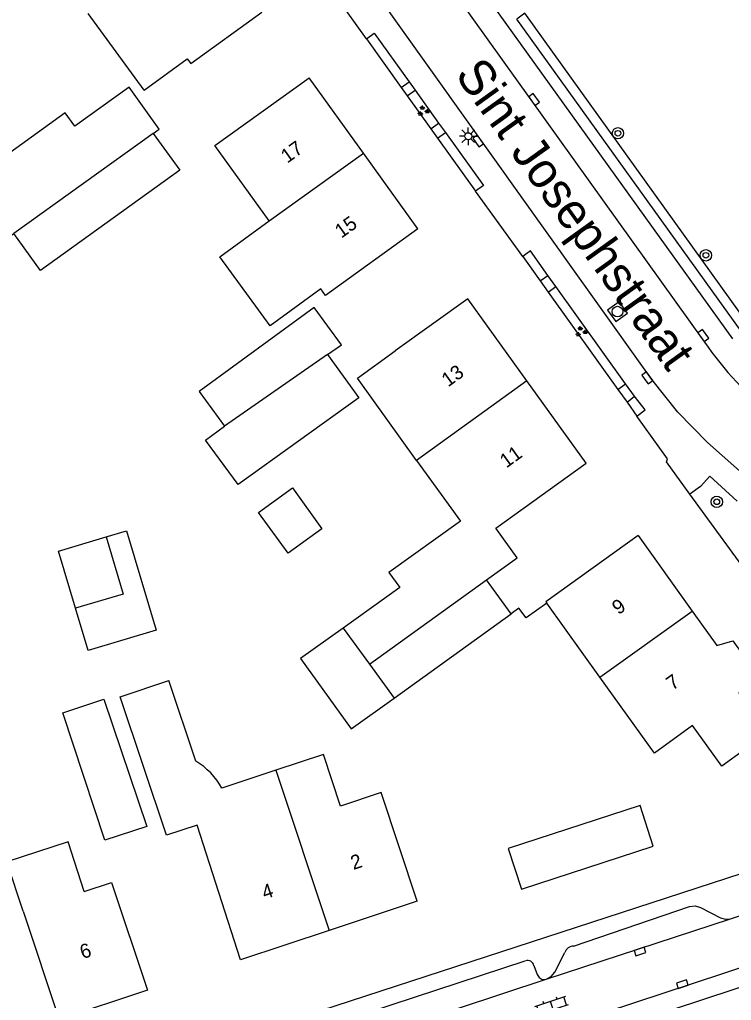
# Model space of a CAD drawing. Extents: x 136000 to 138005, y 398500 to 400500.
# Drawn here: x 137531.8 to 137581.9, y 399032.5 to 399101.6 of the extents above; entities that cross this region are included whole.
import ezdxf

# ---------------------------------------------------------------- set-up
doc = ezdxf.new("R2010")
doc.units = 0
for name, color, linetype in [('gg-afsc-muur', 7, 'Continuous'), ('gg-anno-huisnummerreeks BGT', 7, 'Continuous'), ('gg-anno-openbare ruimte label', 7, 'Continuous'), ('gg-bbg-bijgebouw', 7, 'Continuous'), ('gg-bbg-gedigitaliseerde bebouwing', 7, 'Continuous'), ('gg-bbg-gedigitaliseerde bijgebouw', 7, 'Continuous'), ('gg-bbg-hoofdgebouw', 7, 'Continuous'), ('gg-bbg-luifel en loopbrug', 7, 'Continuous'), ('gg-bbg-tussenscheiding', 7, 'Continuous'), ('gg-knt-verharding', 7, 'Continuous'), ('gg-knt-verharding nz', 7, 'Continuous'), ('gt-grn-groengrens', 7, 'Continuous'), ('gt-symb-boom', 7, 'Continuous'), ('gt-symb-groenvak', 7, 'Continuous'), ('gt-symb-klinker verharding', 7, 'Continuous'), ('gt-symb-kolk', 7, 'Continuous'), ('gt-symb-lichtmast', 7, 'Continuous'), ('gt-symb-rioolschacht', 7, 'Continuous')]:
    doc.layers.add(name, color=color, linetype=linetype)

# ---------------------------------------------------------------- blocks, each defined once
blk = doc.blocks.new('gt0-GRVAK')
at = {"layer": 'gt-symb-groenvak'}
for p, q in [((-0.11, 0.189), (-0.228, 0.24)), ((-0.182, 0.153), (0.088, 0.153)), ((-0.091, 0.211), (-0.156, 0.322)), ((-0.047, 0.214), (-0.047, 0.393)), ((-0.004, 0.211), (0.061, 0.322)), ((0.015, 0.189), (0.133, 0.24)), ((0.262, -0.052), (0.197, 0.059)), ((0.305, -0.049), (0.305, 0.13)), ((0.349, -0.052), (0.414, 0.059)), ((-0.245, -0.228), (-0.363, -0.177)), ((-0.318, -0.264), (-0.047, -0.264)), ((-0.226, -0.206), (-0.291, -0.095)), ((-0.183, -0.203), (-0.183, -0.024)), ((-0.139, -0.206), (-0.074, -0.095)), ((-0.12, -0.228), (-0.002, -0.177)), ((0.243, -0.074), (0.125, -0.023)), ((0.17, -0.11), (0.441, -0.11)), ((0.368, -0.074), (0.486, -0.023))]:
    blk.add_line(p, q, dxfattribs=at)
blk = doc.blocks.new('gt0-LMAST')
at = {"layer": 'gt-symb-lichtmast'}
for p, q in [((-0.182, 0.173), (-0.447, 0.438)), ((-0.005, 0.246), (-0.005, 0.621)), ((0.172, 0.173), (0.437, 0.438)), ((-0.255, -0.004), (-0.63, -0.004)), ((-0.182, -0.181), (-0.447, -0.446)), ((-0.005, -0.254), (-0.005, -0.629)), ((0.437, -0.446), (0.172, -0.181)), ((0.245, -0.004), (0.62, -0.004))]:
    blk.add_line(p, q, dxfattribs=at)
blk.add_circle((-0.005, -0.004), 0.25, dxfattribs=at)
blk = doc.blocks.new('gt0-KOLK')
at = {"layer": 'gt-symb-kolk'}
blk.add_lwpolyline([(0, 0), (0.375, 0), (0.375, 0.4), (-0.375, 0.4), (-0.375, 0), (0, 0)], dxfattribs=at)
blk = doc.blocks.new('gt0-RS')
at = {"layer": 'gt-symb-rioolschacht'}
blk.add_lwpolyline([(-0.5, -0.5), (0.5, -0.5), (0.5, 0.5), (-0.5, 0.5)], close=True, dxfattribs=at)
blk.add_circle((0, 0), 0.375, dxfattribs=at)
blk = doc.blocks.new('gt0-BOOM')
at = {"layer": 'gt-symb-boom'}
for radius in [0.4, 0.2]:
    blk.add_circle((0, 0), radius, dxfattribs=at)
blk = doc.blocks.new('gt0-KL1')
at = {"layer": 'gt-symb-klinker verharding'}
for p, q in [((-1.15, 0.3), (1.15, 0.3)), ((-1, -0.3), (-1, 0.3)), ((-0.5, 0.3), (-0.5, 0.45)), ((0, -0.3), (0, 0.3)), ((0.5, 0.3), (0.5, 0.45)), ((1, -0.3), (1, 0.3)), ((-1.15, -0.3), (1.15, -0.3)), ((-0.5, -0.45), (-0.5, -0.3)), ((0.5, -0.45), (0.5, -0.3))]:
    blk.add_line(p, q, dxfattribs=at)

msp = doc.modelspace()

# ---------------------------------------------------------------- linework, layer by layer
at = {"layer": 'gg-afsc-muur'}
msp.add_lwpolyline([(137568.918, 399060.487), (137567.465, 399059.442), (137566.969, 399060.132), (137566.409, 399059.729)], dxfattribs=at)
at = {"layer": 'gg-bbg-bijgebouw'}
msp.add_line((137566.409, 399059.729), (137564.676, 399062.119), dxfattribs=at)
for points in [[(137537.749, 399053.712), (137540.771, 399044.768), (137537.821, 399043.791)], [(137566.21, 399043.201), (137567.14, 399040.351), (137576.42, 399043.381), (137575.49, 399046.231), (137566.21, 399043.201)]]:
    msp.add_lwpolyline(points, dxfattribs=at)
at = {"layer": 'gg-bbg-gedigitaliseerde bebouwing'}
for p, q in [((137540.57, 399096.59), (137536.636, 399101.984)), ((137563.36, 399081.911), (137558.246, 399078.233)), ((137558.571, 399061.588), (137554.58, 399058.721)), ((137572.656, 399055.278), (137568.918, 399060.487)), ((137576.5, 399049.921), (137572.656, 399055.278)), ((137544.22, 399049.346), (137542.306, 399055.027)), ((137549.848, 399048.715), (137546.04, 399047.451)), ((137536.358, 399040.191), (137538.289, 399040.82))]:
    msp.add_line(p, q, dxfattribs=at)
for points in [[(137549.38, 399087.382), (137545.551, 399092.702), (137552.19, 399097.461)], [(137553.01, 399082.607), (137549.449, 399080.009), (137545.914, 399084.851), (137549.38, 399087.382)], [(137559.764, 399070.533), (137555.597, 399076.328), (137558.246, 399078.233)], [(137559.764, 399070.533), (137562.841, 399066.255), (137557.814, 399062.64), (137558.571, 399061.588)], [(137559.79, 399039.491), (137557.254, 399047.148), (137554.398, 399046.2), (137553.194, 399049.826), (137549.848, 399048.715)], [(137536.358, 399040.191), (137535.222, 399043.677), (137530.899, 399042.268)]]:
    msp.add_lwpolyline(points, dxfattribs=at)
msp.add_arc((137541.806, 399045.206), 4.792, 27.93347, 59.75342, dxfattribs=at)
at = {"layer": 'gg-bbg-gedigitaliseerde bijgebouw'}
msp.add_line((137558.172, 399053.801), (137566.409, 399059.729), dxfattribs=at)
for points in [[(137541.224, 399093.549), (137541.642, 399093.849), (137539.525, 399096.807), (137535.689, 399094.062), (137535.025, 399094.991), (137529.994, 399091.391), (137530.811, 399086.096), (137531.392, 399086.512)], [(137541.224, 399093.549), (137543.093, 399090.951), (137533.277, 399083.891), (137531.392, 399086.512)], [(137553.496, 399077.985), (137554.473, 399078.67), (137552.553, 399081.298), (137544.453, 399075.382), (137546.24, 399072.936)], [(137553.496, 399077.985), (137555.694, 399074.93), (137547.202, 399068.822), (137544.908, 399071.963), (137546.24, 399072.936)], [(137548.631, 399066.865), (137551.024, 399068.587), (137553.091, 399065.713), (137550.719, 399064.007), (137548.631, 399066.865)], [(137535.749, 399060.117), (137534.548, 399064.142), (137537.902, 399065.143)], [(137537.902, 399065.143), (137539.103, 399061.119), (137535.749, 399060.117)], [(137554.58, 399058.721), (137551.595, 399056.577), (137555.151, 399051.627), (137558.172, 399053.801)], [(137537.821, 399043.791), (137534.852, 399052.752), (137537.749, 399053.712)]]:
    msp.add_lwpolyline(points, dxfattribs=at)
at = {"layer": 'gg-bbg-hoofdgebouw'}
for p, q in [((137556.015, 399092.146), (137552.19, 399097.461)), ((137559.84, 399086.831), (137556.015, 399092.146)), ((137567.525, 399076.121), (137563.36, 399081.911)), ((137571.69, 399070.331), (137567.525, 399076.121)), ((137575.36, 399065.231), (137579.17, 399059.906)), ((137579.17, 399059.906), (137580.896, 399057.494)), ((137538.289, 399040.82), (137540.81, 399033.241)), ((137559.79, 399039.491), (137553.6, 399037.436)), ((137553.6, 399037.436), (137547.35, 399035.361)), ((137540.81, 399033.241), (137534.59, 399031.176))]:
    msp.add_line(p, q, dxfattribs=at)
for points in [[(137540.57, 399096.59), (137543.617, 399098.793), (137543.854, 399098.465), (137548.87, 399102.091)], [(137559.84, 399086.831), (137553.344, 399082.146), (137553.01, 399082.607)], [(137564.676, 399062.119), (137566.843, 399063.678), (137565.342, 399065.764), (137571.69, 399070.331)], [(137575.36, 399065.231), (137568.854, 399060.576), (137568.918, 399060.487)], [(137580.896, 399057.494), (137582.026, 399057.83), (137583.33, 399056), (137582.661, 399055.026)], [(137547.35, 399035.361), (137544.3, 399044.855), (137542.158, 399044.158), (137538.885, 399053.874), (137542.306, 399055.027)], [(137582.661, 399055.026), (137582.98, 399054.581), (137582.44, 399054.171), (137584.48, 399051.341), (137581.24, 399049.011), (137579.19, 399051.861), (137576.5, 399049.921)]]:
    msp.add_lwpolyline(points, dxfattribs=at)
at = {"layer": 'gg-bbg-luifel en loopbrug'}
msp.add_lwpolyline([(137537.902, 399065.143), (137539.339, 399065.572), (137541.428, 399058.577), (137536.636, 399057.147), (137535.749, 399060.117)], dxfattribs=at)
at = {"layer": 'gg-bbg-tussenscheiding'}
for p, q in [((137541.224, 399093.549), (137531.392, 399086.512)), ((137549.38, 399087.382), (137556.015, 399092.146)), ((137553.496, 399077.985), (137546.24, 399072.936)), ((137567.525, 399076.121), (137559.764, 399070.533)), ((137556.436, 399056.179), (137564.676, 399062.119)), ((137572.656, 399055.278), (137579.17, 399059.906)), ((137554.58, 399058.721), (137556.436, 399056.179)), ((137556.436, 399056.179), (137558.172, 399053.801)), ((137549.848, 399048.715), (137553.6, 399037.436)), ((137532.052, 399038.788), (137530.899, 399042.268)), ((137532.052, 399038.788), (137534.59, 399031.176))]:
    msp.add_line(p, q, dxfattribs=at)
at = {"layer": 'gg-knt-verharding'}
for p, q in [((137556.226, 399100.194), (137552.819, 399105.012)), ((137558.679, 399096.776), (137559.235, 399097.175)), ((137559.103, 399096.185), (137559.659, 399096.585)), ((137559.235, 399097.175), (137559.659, 399096.585)), ((137559.659, 399096.585), (137561.313, 399094.279)), ((137560.757, 399093.88), (137561.313, 399094.279)), ((137561.313, 399094.279), (137561.785, 399093.621)), ((137561.229, 399093.222), (137561.785, 399093.621)), ((137567.228, 399084.878), (137563.912, 399089.483)), ((137568.457, 399083.163), (137569.003, 399083.556)), ((137569.567, 399082.77), (137569.003, 399083.556)), ((137569.02, 399082.377), (137569.567, 399082.77)), ((137574.477, 399075.923), (137569.567, 399082.77)), ((137573.927, 399075.529), (137574.477, 399075.923)), ((137575.107, 399075.044), (137574.477, 399075.923)), ((137574.575, 399074.625), (137575.107, 399075.044)), ((137581.86, 399038.265), (137590.922, 399041.244)), ((137594.446, 399038.703), (137519.344, 399014.042))]:
    msp.add_line(p, q, dxfattribs=at)
for points in [[(137583.136, 399069.229), (137580.249, 399071.797), (137578.152, 399073.925), (137576.323, 399076.233), (137555.897, 399104.842)], [(137561.686, 399104.447), (137561.932, 399104.278), (137562.21, 399104.171), (137563.825, 399103.897), (137564.191, 399103.756), (137564.47, 399103.48), (137582.012, 399079.081)], [(137586.197, 399075.879), (137584.146, 399077.799), (137582.605, 399079.618), (137566.808, 399101.595)], [(137556.226, 399100.194), (137556.775, 399100.606), (137559.235, 399097.175)], [(137561.785, 399093.621), (137564.469, 399089.878), (137563.912, 399089.483)], [(137569.003, 399083.556), (137567.769, 399085.277), (137567.228, 399084.878)], [(137575.272, 399073.652), (137575.857, 399074.085), (137575.178, 399074.946), (137575.107, 399075.044)], [(137578.996, 399068.152), (137577.356, 399070.418), (137577.419, 399070.64), (137575.272, 399073.652)], [(137582.321, 399067.669), (137580.404, 399069.423), (137579.747, 399068.681), (137578.996, 399068.152)], [(137593.247, 399044.904), (137514.814, 399019.342), (137484.498, 399034.318)], [(137570.806, 399036.34), (137578.981, 399039.126), (137579.375, 399039.175), (137579.756, 399039.06), (137581.166, 399038.321), (137581.508, 399038.237), (137581.86, 399038.265)], [(137510.559, 399009.861), (137516.87, 399011.941), (137577.85, 399031.891), (137594.78, 399037.492)], [(137568.892, 399034.003), (137569.235, 399034.201), (137569.483, 399034.509), (137570.205, 399035.898)], [(137518.519, 399017.445), (137518.783, 399017.635), (137518.968, 399017.901), (137519.936, 399019.642), (137520.269, 399019.833), (137567.415, 399035.293)], [(137568.014, 399034.968), (137568.257, 399034.33), (137568.385, 399034.116), (137568.602, 399033.992), (137568.892, 399034.003)]]:
    msp.add_lwpolyline(points, dxfattribs=at)
for centre, radius, start, end in [((137570.833, 399035.674), 0.667, 92.31439, 160.35018), ((137567.583, 399034.887), 0.439, 10.60345, 112.4306)]:
    msp.add_arc(centre, radius, start, end, dxfattribs=at)
at = {"layer": 'gg-knt-verharding nz'}
for p, q in [((137561.686, 399104.447), (137580.027, 399078.86)), ((137568.892, 399034.003), (137581.86, 399038.265)), ((137518.519, 399017.445), (137568.892, 399034.003))]:
    msp.add_line(p, q, dxfattribs=at)
msp.add_arc((137600.026, 399092.636), 24.284, 214.56085, 231.58329, dxfattribs=at)
at = {"layer": 'gt-grn-groengrens'}
for p, q in [((137556.226, 399100.194), (137558.679, 399096.776)), ((137558.679, 399096.776), (137559.103, 399096.185)), ((137559.103, 399096.185), (137560.757, 399093.88)), ((137560.757, 399093.88), (137561.229, 399093.222)), ((137561.229, 399093.222), (137563.912, 399089.483)), ((137567.228, 399084.878), (137568.457, 399083.163)), ((137568.457, 399083.163), (137569.02, 399082.377)), ((137569.02, 399082.377), (137573.927, 399075.529)), ((137573.927, 399075.529), (137574.575, 399074.625)), ((137574.575, 399074.625), (137575.272, 399073.652)), ((137583.869, 399061.452), (137578.996, 399068.152))]:
    msp.add_line(p, q, dxfattribs=at)
msp.add_lwpolyline([(137586.654, 399076.41), (137584.654, 399078.282), (137583.157, 399080.049), (137567.377, 399102.004), (137566.808, 399101.595)], dxfattribs=at)

# ---------------------------------------------------------------- block references
at = {"layer": 'gt-symb-boom'}
for p in [(137573.933, 399093.555), (137580.128, 399084.966), (137580.895, 399067.614)]:
    msp.add_blockref('gt0-BOOM', p, dxfattribs=at)
at = {"layer": 'gt-symb-groenvak'}
for p in [(137560.215, 399095.124), (137571.333, 399079.587)]:
    msp.add_blockref('gt0-GRVAK', p, dxfattribs=at)
at = {"layer": 'gt-symb-klinker verharding', "rotation": 18.181268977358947}
msp.add_blockref('gt0-KL1', (137569.278, 399032.162), dxfattribs=at)
at = {"layer": 'gt-symb-kolk'}
for p, rotation in [((137567.869, 399095.827), -54.48230213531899), ((137563.93, 399092.898), -54.48230213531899), ((137579.782, 399079.204), -54.14945188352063), ((137575.839, 399076.22), -54.27586519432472), ((137575.549, 399035.769), 18.000074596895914), ((137578.529, 399033.476), 18.23569146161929)]:
    msp.add_blockref('gt0-KOLK', p, dxfattribs=dict(at, rotation=rotation))
at = {"layer": 'gt-symb-lichtmast'}
msp.add_blockref('gt0-LMAST', (137563.403, 399093.354), dxfattribs=at)
at = {"layer": 'gt-symb-rioolschacht', "rotation": -53.989474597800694}
msp.add_blockref('gt0-RS', (137573.901, 399081.004), dxfattribs=at)

# ---------------------------------------------------------------- texts
at = {"layer": 'gg-anno-huisnummerreeks BGT'}
for s, rotation, p in [('17', 35.7, (137550.657, 399091.413)), ('15', 35.7, (137554.459, 399086.13)), ('13', 35.7, (137561.973, 399075.659)), ('11', 35.7, (137566.076, 399069.955)), ('9', 35.6, (137573.974, 399059.626)), ('7', 35.6, (137577.783, 399054.302)), ('2', 18.4, (137555.31, 399041.691)), ('4', 18.4, (137549.059, 399039.615)), ('6', 18.4, (137536.25, 399035.414))]:
    msp.add_text(s, height=1, rotation=rotation, dxfattribs=at).set_placement(p)
at = {"layer": 'gg-anno-openbare ruimte label'}
msp.add_text('Sint Josephstraat', height=2.5, rotation=305.7, dxfattribs=at).set_placement((137562.406, 399097.671))

doc.saveas('drawing.dxf')
